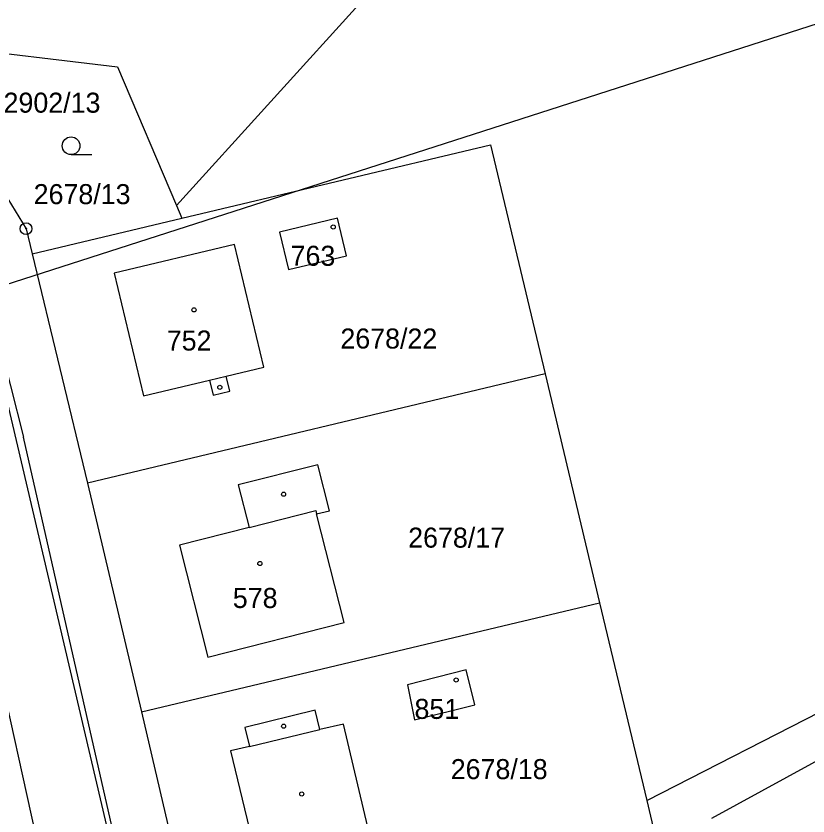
# Model space of a CAD drawing. Extents: x -758836 to -757729, y -1175316 to -1174366.
# Drawn here: x -758356.4 to -758289.2, y -1174936.9 to -1174869 of the extents above; entities that cross this region are included whole.
import ezdxf

# ---------------------------------------------------------------- set-up
doc = ezdxf.new("R2010")
doc.units = 0
for name, color, linetype in [('_NOR-pomocná', 7, 'Continuous'), ('Hranice parcel', 7, 'Continuous'), ('Parcelní čísla', 7, 'Continuous'), ('Vnitřní kresba', 7, 'Continuous'), ('Značky bodu BP', 7, 'Continuous'), ('Značky budov', 7, 'Continuous'), ('Značky kultur', 7, 'Continuous')]:
    doc.layers.add(name, color=color, linetype=linetype)

msp = doc.modelspace()

# ---------------------------------------------------------------- linework, layer by layer
at = {"layer": '_NOR-pomocná'}
msp.add_lwpolyline([(-758417.595, -1174755.224), (-758317.652, -1174723.031), (-758272.123, -1174864.38), (-758372.066, -1174896.572)], close=True, dxfattribs=at)
at = {"layer": 'Hranice parcel'}
for p, q in [((-758310.72, -1174849.73), (-758342.82, -1174885.08)), ((-758342.82, -1174885.08), (-758342.36, -1174886.17)), ((-758355.06, -1174889.19), (-758342.36, -1174886.17)), ((-758355.06, -1174889.19), (-758350.37, -1174908.66)), ((-758311.55, -1174899.38), (-758350.37, -1174908.66)), ((-758311.55, -1174899.38), (-758306.92, -1174918.8)), ((-758350.37, -1174908.66), (-758345.78, -1174928.06)), ((-758345.78, -1174928.06), (-758306.92, -1174918.8)), ((-758306.92, -1174918.8), (-758302.92, -1174935.57)), ((-758345.78, -1174928.06), (-758341.26, -1174947.41)), ((-758302.92, -1174935.57), (-758302.28, -1174938.23))]:
    msp.add_line(p, q, dxfattribs=at)
for points in [[(-758362.51, -1174871.59), (-758347.81, -1174873.33), (-758342.82, -1174885.08)], [(-758342.36, -1174886.17), (-758316.19, -1174879.95), (-758311.55, -1174899.38)], [(-758359.63, -1174880.45), (-758355.57, -1174887.06), (-758355.06, -1174889.19)], [(-758297.139, -1175157.069), (-758301.82, -1175137.17), (-758334.58, -1174998.03), (-758360.35, -1174888.27), (-758361.81, -1174882.07)], [(-758302.92, -1174935.57), (-758286.99, -1174927.44), (-758267.9, -1174916.47), (-758249.14, -1174905.98), (-758236.24, -1174897.16), (-758223.14, -1174884.37)], [(-758333.32, -1174890.52), (-758328.39, -1174889.35), (-758329.14, -1174886.18), (-758334.07, -1174887.35), (-758333.32, -1174890.52)], [(-758345.61, -1174901.23), (-758340, -1174899.9), (-758339.69, -1174901.18), (-758338.3, -1174900.85), (-758338.6, -1174899.57), (-758335.39, -1174898.81), (-758337.88, -1174888.4), (-758348.1, -1174890.84), (-758345.61, -1174901.23)], [(-758336.66, -1174912.42), (-758342.55, -1174913.91), (-758340.14, -1174923.41), (-758328.59, -1174920.48), (-758330.93, -1174911.26), (-758329.84, -1174910.99), (-758330.83, -1174907.09), (-758337.58, -1174908.8), (-758336.66, -1174912.42)], [(-758297.41, -1174937.08), (-758278.62, -1174926.8), (-758276.96, -1174925.54), (-758269.21, -1174920.77)], [(-758318.24, -1174924.5), (-758323.22, -1174925.76), (-758322.61, -1174928.72), (-758317.51, -1174927.47), (-758318.24, -1174924.5)], [(-758326.1, -1174939.86), (-758328.65, -1174929.09), (-758330.65, -1174929.56), (-758331.04, -1174927.9), (-758337.01, -1174929.38), (-758336.63, -1174930.98), (-758338.22, -1174931.36), (-758335.63, -1174942.14), (-758326.1, -1174939.86)]]:
    msp.add_lwpolyline(points, dxfattribs=at)
at = {"layer": 'Vnitřní kresba'}
for p, q in [((-758358.45, -1174894.31), (-758355.8, -1174904.75)), ((-758340, -1174899.9), (-758338.6, -1174899.57)), ((-758334.58, -1174998.03), (-758355.8, -1174904.75)), ((-758341.2, -1174999.31), (-758361.89, -1174906.28)), ((-758336.66, -1174912.42), (-758331, -1174910.98)), ((-758331, -1174910.98), (-758330.93, -1174911.26)), ((-758336.63, -1174930.98), (-758330.65, -1174929.56))]:
    msp.add_line(p, q, dxfattribs=at)
at = {"layer": 'Značky bodu BP'}
for radius in [0.5, 0.0303]:
    msp.add_circle((-758355.57, -1174887.06), radius, dxfattribs=at)
at = {"layer": 'Značky budov'}
for centre in [(-758329.517, -1174886.919), (-758341.327, -1174893.949), (-758339.137, -1174900.519), (-758333.727, -1174909.589), (-758335.737, -1174915.469), (-758319.087, -1174925.349), (-758333.727, -1174929.269), (-758332.187, -1174935.019)]:
    msp.add_circle(centre, 0.175, dxfattribs=at)
at = {"layer": 'Značky kultur'}
msp.add_line((-758351.753, -1174880.78), (-758350.003, -1174880.78), dxfattribs=at)
msp.add_circle((-758351.753, -1174880.03), 0.75, dxfattribs=at)

# ---------------------------------------------------------------- texts
at = {"layer": 'Parcelní čísla'}
for s, p in [('2902/13', (-758357.48, -1174877.22)), ('2678/13', (-758354.928, -1174884.98)), ('763', (-758333.134, -1174890.21)), ('2678/22', (-758328.908, -1174897.23)), ('752', (-758343.634, -1174897.4)), ('2678/17', (-758323.158, -1174914.12)), ('578', (-758338.034, -1174919.24)), ('851', (-758322.624, -1174928.65)), ('2678/18', (-758319.548, -1174933.76))]:
    msp.add_text(s, height=1.7, dxfattribs=at).set_placement(p)

doc.saveas('drawing.dxf')
